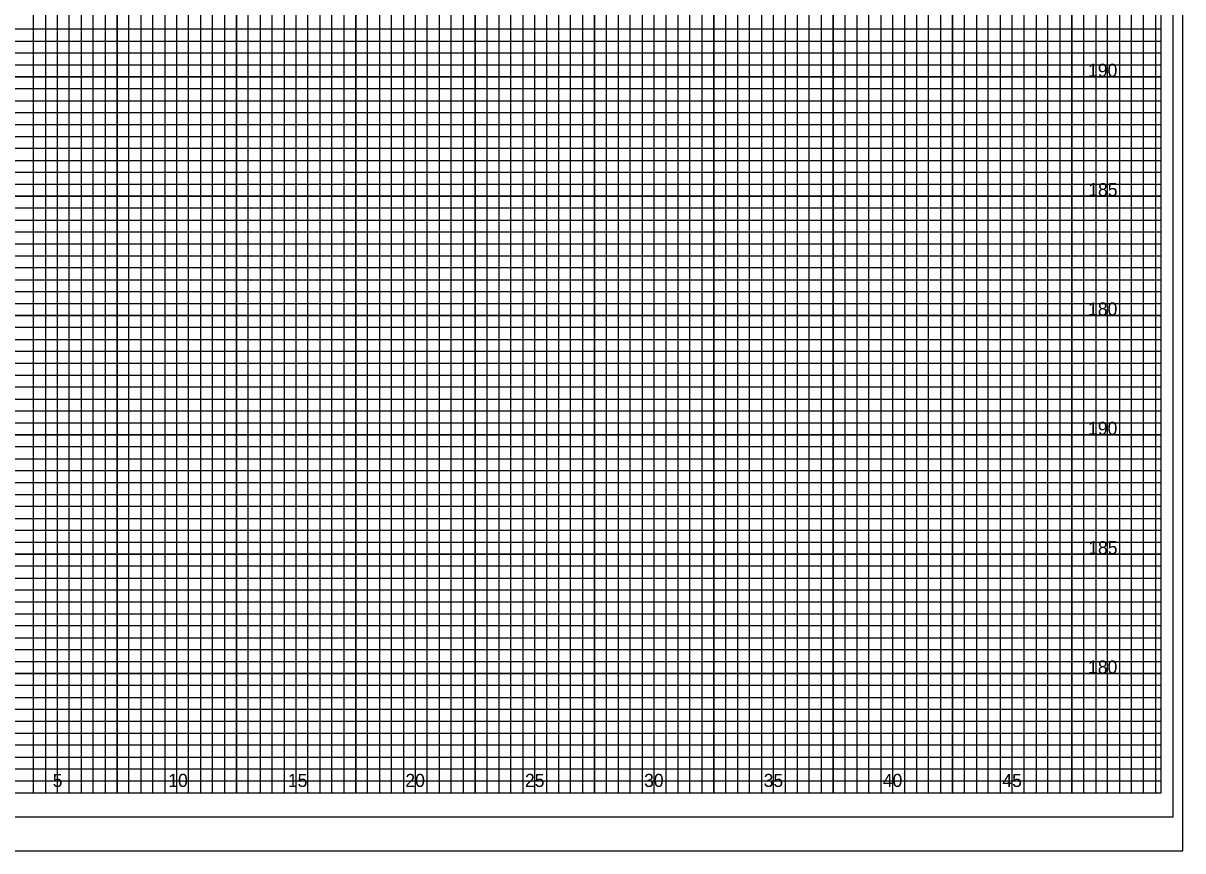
# Model space of a CAD drawing. Extents: x -4 to 103, y -2 to 6583.
# Drawn here: x 54.82 to 103.4, y 776.65 to 811.33 of the extents above; entities that cross this region are included whole.
import ezdxf

# ---------------------------------------------------------------- set-up
doc = ezdxf.new("R2010")
doc.units = 0
for name, color, linetype in [('Prop XS Elevation Labels', 7, 'Continuous'), ('Prop XS Offset Labels', 7, 'Continuous'), ('Sheet Cross Section CELL', 7, 'Continuous'), ('Sheet Cross Section Grid Major CELL', 7, 'Continuous'), ('Sheet Cross Section Grid Middle CELL', 7, 'Continuous'), ('Sheet Cutting Line CELL', 7, 'Continuous'), ('Sheet DOT Grid CELL', 7, 'Continuous'), ('Sheet Plot Border Inside CELL', 7, 'Continuous'), ('Sheet Plot Border Outside CELL', 7, 'Continuous')]:
    doc.layers.add(name, color=color, linetype=linetype)

msp = doc.modelspace()

# ---------------------------------------------------------------- linework, layer by layer
at = {"layer": 'Sheet Cross Section CELL'}
msp.add_lwpolyline([(102.5, 844.075), (0, 844.075), (0, 779.075), (102.5, 779.075)], close=True, dxfattribs=at)
at = {"layer": 'Sheet Cross Section Grid Major CELL'}
for points in [[(56.25, 779.075), (56.25, 844.075)], [(58.75, 844.075), (58.75, 779.075), (61.25, 779.075), (61.25, 844.075)], [(63.75, 844.075), (63.75, 779.075), (66.25, 779.075), (66.25, 844.075)], [(68.75, 844.075), (68.75, 779.075), (71.25, 779.075), (71.25, 844.075)], [(73.75, 844.075), (73.75, 779.075), (76.25, 779.075), (76.25, 841.075)], [(88.75, 841.075), (88.75, 779.075), (91.25, 779.075), (91.25, 842.5)], [(93.75, 842.5), (93.75, 779.075), (96.25, 779.075), (96.25, 842.5)], [(98.75, 842.5), (98.75, 779.075), (101.25, 779.075), (101.25, 842.5)], [(78.75, 841.075), (78.75, 779.075), (81.25, 779.075), (81.25, 841.075)], [(83.75, 841.075), (83.75, 779.075), (86.25, 779.075), (86.25, 841.075)], [(0, 806.575), (102.5, 806.575), (102.5, 809.075), (0, 809.075)], [(0, 801.575), (102.5, 801.575), (102.5, 804.075), (0, 804.075)], [(0, 796.575), (102.5, 796.575), (102.5, 799.075), (0, 799.075)], [(0, 791.575), (102.5, 791.575), (102.5, 794.075), (0, 794.075)], [(0, 786.575), (102.5, 786.575), (102.5, 789.075), (0, 789.075)], [(0, 781.575), (102.5, 781.575), (102.5, 784.075), (0, 784.075)]]:
    msp.add_lwpolyline(points, dxfattribs=at)
at = {"layer": 'Sheet Cross Section Grid Middle CELL'}
for points in [[(54.75, 779.075), (55.25, 779.075), (55.25, 844.075)], [(55.75, 844.075), (55.75, 779.075), (56.75, 779.075), (56.75, 844.075)], [(57.25, 844.075), (57.25, 779.075), (57.75, 779.075), (57.75, 844.075)], [(58.25, 844.075), (58.25, 779.075), (59.25, 779.075), (59.25, 844.075)], [(59.75, 844.075), (59.75, 779.075), (60.25, 779.075), (60.25, 844.075)], [(60.75, 844.075), (60.75, 779.075), (61.75, 779.075), (61.75, 844.075)], [(62.25, 844.075), (62.25, 779.075), (62.75, 779.075), (62.75, 844.075)], [(63.25, 844.075), (63.25, 779.075), (64.25, 779.075), (64.25, 844.075)], [(64.75, 844.075), (64.75, 779.075), (65.25, 779.075), (65.25, 844.075)], [(65.75, 844.075), (65.75, 779.075), (66.75, 779.075), (66.75, 844.075)], [(67.25, 844.075), (67.25, 779.075), (67.75, 779.075), (67.75, 844.075)], [(68.25, 844.075), (68.25, 779.075), (69.25, 779.075), (69.25, 844.075)], [(69.75, 844.075), (69.75, 779.075), (70.25, 779.075), (70.25, 844.075)], [(70.75, 844.075), (70.75, 779.075), (71.75, 779.075), (71.75, 844.075)], [(72.25, 844.075), (72.25, 779.075), (72.75, 779.075), (72.75, 844.075)], [(73.25, 844.075), (73.25, 779.075), (74.25, 779.075), (74.25, 841.075)], [(89.75, 841.075), (89.75, 779.075), (90.25, 779.075), (90.25, 842.5)], [(90.75, 842.5), (90.75, 779.075), (91.75, 779.075), (91.75, 842.5)], [(92.25, 842.5), (92.25, 779.075), (92.75, 779.075), (92.75, 842.5)], [(93.25, 842.5), (93.25, 779.075), (94.25, 779.075), (94.25, 842.5)], [(94.75, 842.5), (94.75, 779.075), (95.25, 779.075), (95.25, 842.5)], [(95.75, 842.5), (95.75, 779.075), (96.75, 779.075), (96.75, 842.5)], [(97.25, 842.5), (97.25, 779.075), (97.75, 779.075), (97.75, 842.5)], [(98.25, 842.5), (98.25, 779.075), (99.25, 779.075), (99.25, 842.5)], [(99.75, 842.5), (99.75, 779.075), (100.25, 779.075), (100.25, 842.5)], [(100.25, 842.5), (100.75, 842.5), (100.75, 779.075), (101.75, 779.075), (101.75, 842.5), (102.25, 842.5), (102.25, 779.075)], [(74.75, 841.075), (74.75, 779.075), (75.25, 779.075), (75.25, 841.075)], [(75.75, 841.075), (75.75, 779.075), (76.75, 779.075), (76.75, 841.075)], [(77.25, 841.075), (77.25, 779.075), (77.75, 779.075), (77.75, 841.075)], [(78.25, 841.075), (78.25, 779.075), (79.25, 779.075), (79.25, 841.075)], [(79.75, 841.075), (79.75, 779.075), (80.25, 779.075), (80.25, 841.075)], [(80.75, 841.075), (80.75, 779.075), (81.75, 779.075), (81.75, 841.075)], [(82.25, 841.075), (82.25, 779.075), (82.75, 779.075), (82.75, 841.075)], [(83.25, 841.075), (83.25, 779.075), (84.25, 779.075), (84.25, 841.075)], [(84.75, 841.075), (84.75, 779.075), (85.25, 779.075), (85.25, 841.075)], [(85.75, 841.075), (85.75, 779.075), (86.75, 779.075), (86.75, 841.075)], [(87.25, 841.075), (87.25, 779.075), (87.75, 779.075), (87.75, 841.075)], [(88.25, 841.075), (88.25, 779.075), (89.25, 779.075), (89.25, 841.075)], [(0, 810.575), (102.5, 810.575), (102.5, 811.075), (0, 811.075)], [(0, 809.575), (102.5, 809.575), (102.5, 810.075), (0, 810.075)], [(0, 808.075), (102.5, 808.075), (102.5, 808.575), (0, 808.575)], [(0, 807.075), (102.5, 807.075), (102.5, 807.575), (0, 807.575)], [(0, 805.575), (102.5, 805.575), (102.5, 806.075), (0, 806.075)], [(0, 804.575), (102.5, 804.575), (102.5, 805.075), (0, 805.075)], [(0, 803.075), (102.5, 803.075), (102.5, 803.575), (0, 803.575)], [(0, 802.075), (102.5, 802.075), (102.5, 802.575), (0, 802.575)], [(0, 800.575), (102.5, 800.575), (102.5, 801.075), (0, 801.075)], [(0, 799.575), (102.5, 799.575), (102.5, 800.075), (0, 800.075)], [(0, 798.075), (102.5, 798.075), (102.5, 798.575), (0, 798.575)], [(0, 797.075), (102.5, 797.075), (102.5, 797.575), (0, 797.575)], [(0, 795.575), (102.5, 795.575), (102.5, 796.075), (0, 796.075)], [(0, 794.575), (102.5, 794.575), (102.5, 795.075), (0, 795.075)], [(0, 793.075), (102.5, 793.075), (102.5, 793.575), (0, 793.575)], [(0, 792.075), (102.5, 792.075), (102.5, 792.575), (0, 792.575)], [(0, 790.575), (102.5, 790.575), (102.5, 791.075), (0, 791.075)], [(0, 789.575), (102.5, 789.575), (102.5, 790.075), (0, 790.075)], [(0, 788.075), (102.5, 788.075), (102.5, 788.575), (0, 788.575)], [(0, 787.075), (102.5, 787.075), (102.5, 787.575), (0, 787.575)], [(0, 785.575), (102.5, 785.575), (102.5, 786.075), (0, 786.075)], [(0, 784.575), (102.5, 784.575), (102.5, 785.075), (0, 785.075)], [(0, 783.075), (102.5, 783.075), (102.5, 783.575), (0, 783.575)], [(0, 782.075), (102.5, 782.075), (102.5, 782.575), (0, 782.575)], [(0, 780.575), (102.5, 780.575), (102.5, 781.075), (0, 781.075)], [(0, 779.575), (102.5, 779.575), (102.5, 780.075), (0, 780.075)]]:
    msp.add_lwpolyline(points, dxfattribs=at)
at = {"layer": 'Sheet Cutting Line CELL'}
msp.add_line((-3.5, 776.65), (103.4, 776.65), dxfattribs=at)
at = {"layer": 'Sheet DOT Grid CELL'}
for p, q in [((56.25, 779.075), (56.25, 844.075)), ((58.75, 779.075), (58.75, 844.075)), ((61.25, 779.075), (61.25, 844.075)), ((63.75, 779.075), (63.75, 844.075)), ((66.25, 779.075), (66.25, 844.075)), ((68.75, 779.075), (68.75, 844.075)), ((71.25, 779.075), (71.25, 844.075)), ((73.75, 779.075), (73.75, 844.075)), ((91.25, 779.075), (91.25, 842.5)), ((93.75, 779.075), (93.75, 842.5)), ((96.25, 779.075), (96.25, 842.5)), ((98.75, 779.075), (98.75, 842.5)), ((101.25, 779.075), (101.25, 842.5)), ((76.25, 779.075), (76.25, 841.075)), ((78.75, 779.075), (78.75, 841.075)), ((81.25, 779.075), (81.25, 841.075)), ((83.75, 779.075), (83.75, 841.075)), ((86.25, 779.075), (86.25, 841.075)), ((88.75, 779.075), (88.75, 841.075)), ((0, 809.075), (102.5, 809.075)), ((0, 806.575), (102.5, 806.575)), ((0, 804.075), (102.5, 804.075)), ((0, 801.575), (102.5, 801.575)), ((0, 799.075), (102.5, 799.075)), ((0, 796.575), (102.5, 796.575)), ((0, 794.075), (102.5, 794.075)), ((0, 791.575), (102.5, 791.575)), ((0, 789.075), (102.5, 789.075)), ((0, 786.575), (102.5, 786.575)), ((0, 784.075), (102.5, 784.075)), ((0, 781.575), (102.5, 781.575))]:
    msp.add_line(p, q, dxfattribs=at)
at = {"layer": 'Sheet Plot Border Inside CELL'}
msp.add_lwpolyline([(103, 845.075), (-2.8, 845.075), (-2.8, 778.075), (103, 778.075)], close=True, dxfattribs=at)
at = {"layer": 'Sheet Plot Border Outside CELL'}
msp.add_lwpolyline([(103.4, 846.475), (-3.5, 846.475), (-3.5, 776.65), (103.4, 776.65)], close=True, dxfattribs=at)

# ---------------------------------------------------------------- texts
at = {"layer": 'Prop XS Elevation Labels'}
for s, p in [('190', (99.43, 809.075)), ('185', (99.438, 804.075)), ('180', (99.43, 799.075)), ('190', (99.43, 794.075)), ('185', (99.438, 789.075)), ('180', (99.43, 784.075))]:
    msp.add_text(s, height=0.55, dxfattribs=at).set_placement(p)
at = {"layer": 'Prop XS Offset Labels'}
for s, p in [('5', (56.057, 779.325)), ('10', (60.897, 779.325)), ('15', (65.906, 779.325)), ('20', (70.831, 779.325)), ('25', (75.84, 779.325)), ('30', (80.831, 779.325)), ('35', (85.84, 779.325)), ('40', (90.831, 779.325)), ('45', (95.84, 779.325))]:
    msp.add_text(s, height=0.55, dxfattribs=at).set_placement(p)

doc.saveas('drawing.dxf')
